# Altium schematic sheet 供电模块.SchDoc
size 381 x 241 mm; SheetNumber: 1; SheetTotal: 2
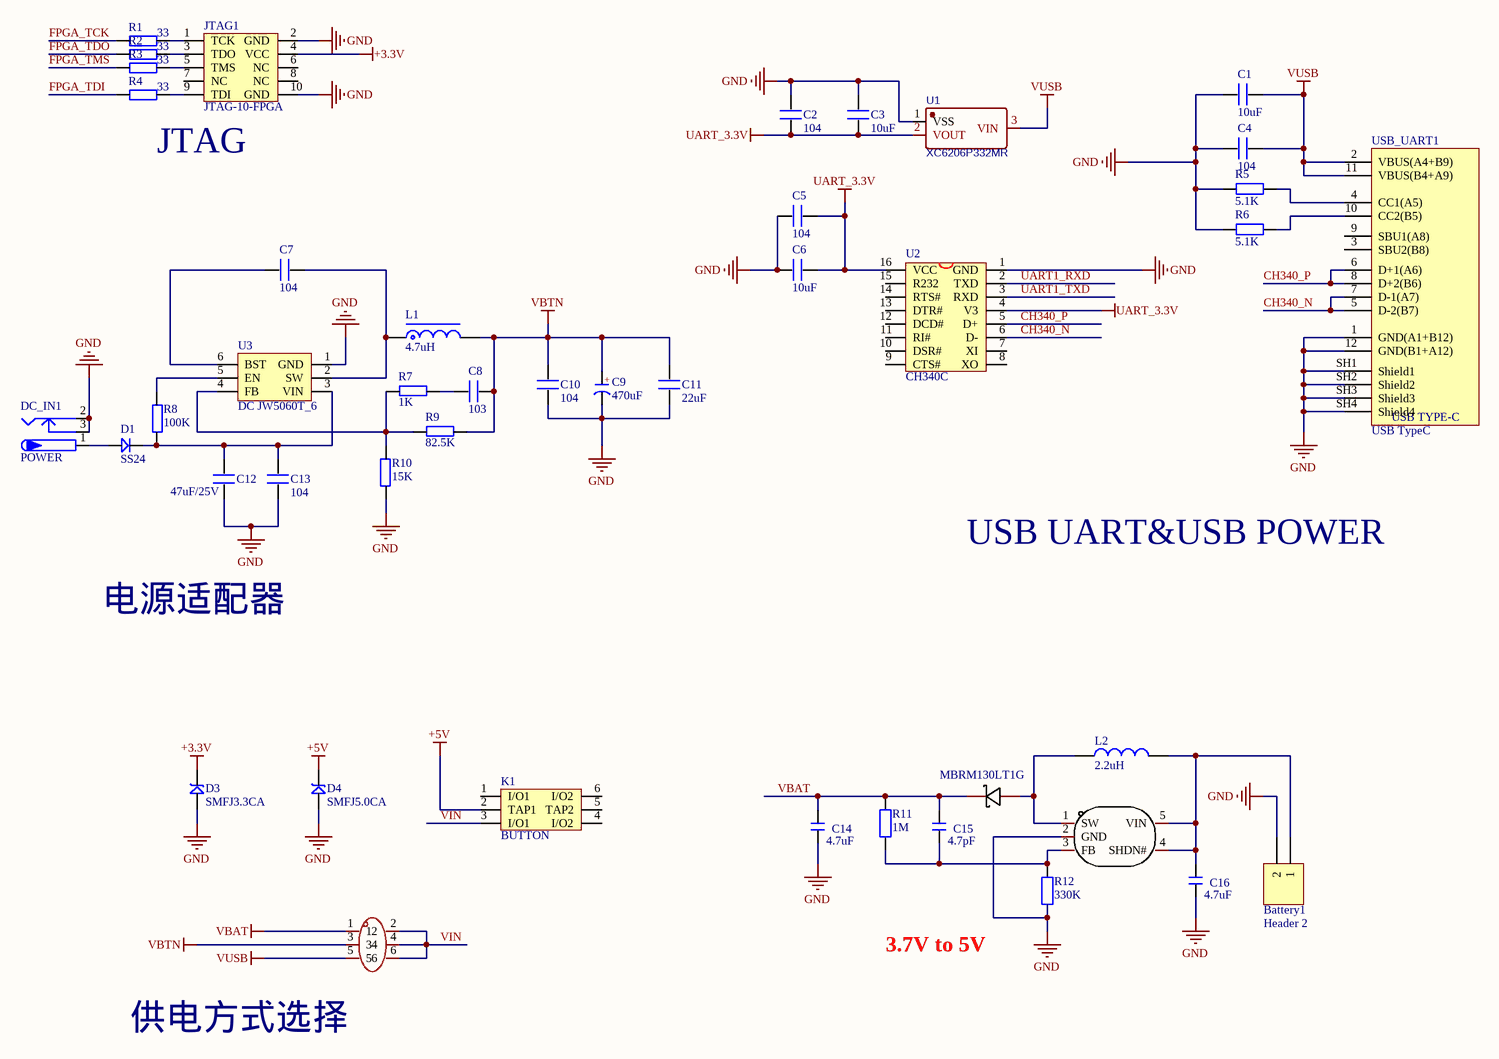
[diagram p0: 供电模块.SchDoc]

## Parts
Battery1  Header 2  [HDR1X2]
C1  10uF  [0603P]
C2  104  [0603P]
C3  10uF  [0603P]
C4  104  [0603P]
C5  104  [0603P]
C6  10uF  [0603P]
C7  104  [0603P]
C8  103  [0603P]
C9  470uF  [CM D(6.3*5.4)]
C10  104  [0603P]
C11  22uF  [0603P]
C12  47uF/25V  [0603P]
C13  104  [0603P]
C14  4.7uF  [C 0603_M]
C15  4.7pF  [C 0603_M]
C16  4.7uF  [C 0603_M]
D1  SS24  [SMA]
D2  MBRM130LT1G  [DIO-SMD_L2.0-W1.9-LS3.8-RD]
D3  SMFJ3.3CA  [SOD-123]
D4  SMFJ5.0CA  [SOD-123]
DC_IN1  POWER  [DC10B]
H1  PZ254V-12-6P  [HDR-TH_6P-P2.54-V-M-R2-C3-S2.54]  (value not drawn)
JTAG1  JTAG-10-FPGA  [HDR-IDC-SMD_10PIN-V-ROW2-COL5-PITCH2.00]
K1  BUTTON  [BTN8.5*8.5]
L1  4.7uH  [L-SMD-0420]
L2  2.2uH  [NR6028]
R1  33  [0402]
R2  33  [0402]
R3  33  [0402]
R4  33  [0402]
R5  5.1K  [R 0603_M]
R6  5.1K  [R 0603_M]
R7  1K  [0603P]
R8  100K  [0603P]
R9  82.5K  [0603P]
R10  15K  [0603P]
R11  1M  [R 0603_M]
R12  330K  [R 0603_M]
U1  XC6206P332MR  [SOT-23]
U2  CH340C  [SOP16M]
U3  DC JW5060T_6  [SOT23-6N]
U4  LM2704MF-ADJ/NOPB  [SOT-23-5_L3.0-W1.7-P0.95-LS2.8-BR]  (value not drawn)
USB_UART1  USB TypeC  [USB TYPE-C - 10*9]

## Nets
+3.3V: D3.2 JTAG1.4(VCC)
+5V: D4.2 K1.2(TAP1)
GND: Battery1.2 C1.1 C2.1 C3.1 C4.1 C5.2 C6.2 C9.2(K) C10.2 C11.2 C12.1 C13.1 C14.2 C16.2 D3.1 D4.1 DC_IN1.2 DC_IN1.3 JTAG1.2(GND) JTAG1.10(GND) R5.2 R6.2 R10.2 R12.1 U1.1(VSS) U2.1(GND) U3.1(GND) U4.2(GND) USB_UART1.1(GND(A1+B12)) USB_UART1.12(GND(B1+A12)) USB_UART1.SH1(Shield1) USB_UART1.SH2(Shield2) USB_UART1.SH3(Shield3) USB_UART1.SH4(Shield4)
UART_3.3V: C2.2 C3.2 C5.1 C6.1 U1.2(VOUT) U2.4(V3) U2.16(VCC)
VBAT: C14.1 C15.1 D2.1(C) H1.1 R11.2
VBTN: C8.1 C9.1(A) C10.1 C11.1 H1.3 L1.2 R9.1
VUSB: C1.2 C4.2 H1.5 U1.3(VIN) USB_UART1.2(VBUS(A4+B9)) USB_UART1.11(VBUS(B4+A9))
CH340_N: U2.6(D-) USB_UART1.5(D-2(B7)) USB_UART1.7(D-1(A7))
CH340_P: U2.5(D+) USB_UART1.6(D+1(A6)) USB_UART1.8(D+2(B6))
FPGA_TCK: R1.1
FPGA_TDI: R4.1
FPGA_TDO: R2.1
FPGA_TMS: R3.1
UART1_RXD: U2.2(TXD)
UART1_TXD: U2.3(RXD)
VIN: H1.2 H1.4 H1.6 K1.3(I/O1)
NetBattery1_1: Battery1.1 C16.1 L2.1 U4.4(SHDN#) U4.5(VIN)
NetC7_1: C7.1 L1.1 U3.2(SW)
NetC7_2: C7.2 U3.6(BST)
NetC8_2: C8.2 R7.1
NetC12_2: C12.2 C13.2 D1.2(K) R8.1 U3.3(VIN)
NetC15_2: C15.2 R11.1 R12.2 U4.3(FB)
NetD1_1: D1.1(A) DC_IN1.1
NetD2_2: D2.2(A) L2.2 U4.1(SW)
NetJTAG1_1: JTAG1.1(TCK) R1.2
NetJTAG1_3: JTAG1.3(TDO) R2.2
NetJTAG1_5: JTAG1.5(TMS) R3.2
NetJTAG1_9: JTAG1.9(TDI) R4.2
NetR5_1: R5.1 USB_UART1.4(CC1(A5))
NetR6_1: R6.1 USB_UART1.10(CC2(B5))
NetR7_2: R7.2 R9.2 R10.1 U3.4(FB)
NetR8_2: R8.2 U3.5(EN)

Not connected (* = marked no-connect by the designer): JTAG1 6(NC) 7(NC) 8(NC); K1 1(I/O1) 4(I/O2) 5(TAP2) 6(I/O2); U2 7(XI) 8(XO) 9(CTS#) 10(DSR#) 11(RI#) 12(DCD#) 13(DTR#) 14(RTS#) 15(R232); USB_UART1 3(SBU2(B8)) 9(SBU1(A8))

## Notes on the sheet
- JTAG
- USB UART&USB POWER
- 电源适配器
- 3.7V to 5V
- 供电方式选择

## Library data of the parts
Battery1 = Header 2: Header, 2-Pin
C1-C8 C10-C13 = C
C9 = C-CM: 贴片电解电容; 版权归属: 源创客
C14-C16 = C: 无极性贴片电容; 版权归属: 源创客
D1 = SS14: 肖特基二极管; 版权归属: 源创客; 属性: 40V/1A
D2 = MBRM130LT1G: Manufacturer: onsemi(安森美); Add into BOM: yes; Forward Voltage (Vf@If): 380mV@1A; Reverse Voltage (Vr): 30V; Average Rectified Current (Io): 1A; Reverse Leakage Current (Ir): 410uA@30V
D3 D4 = SMBJ: TVS
DC_IN1 = P-DC: 低压电源接口; BOM名称: DC电源接口; 版权归属: 源创客
H1 = PZ254V-12-6P: Manufacturer: XFCN(兴飞); Add into BOM: yes; Pin Structure: 2x3P; Pitch: 2.54mm; Circluar Pins/Square Pins: 方针
L1 = L-CDRH: 功率屏蔽电感; 版权归属: 源创客
L2 = L: 小功率贴片电感; 淘宝ID: 封装库来自淘宝 ID：黄晶宝石; 封装库来自淘宝卖家 ID：黄晶宝石: 其他店铺购入均为盗版，不享受售后技术支持服务，请立即申请退款
R1-R4 R7-R10 = R
R5 R6 R11 R12 = R: 贴片电阻; 版权归属: 来自淘宝 ID：黄晶宝石; 封装库来自淘宝卖家 ID：黄晶宝石: 其他店铺购入均为盗版，不享受售后技术支持服务，请立即申请退款
U1 = XC6206P332MR_C347376: BOM_Manufacturer: Youtai Semiconductor Co., Ltd.; Contributor: LCSC; SMT Type: Extend
U2 = CH340G: USB2UART
U3 = DC JW5060T_6: DC降压芯片
U4 = LM2704MF-ADJ/NOPB: Manufacturer: TI(德州仪器); Add into BOM: yes; Function: 升压型; Input Voltage: 2.2V~7V; Output Voltage: 20V; Output Current (Max): 550mA; Synchronous Rectification: 否; Number of Outputs: 1; Topology: 升压式; Switch tube (built-in/external): 内置
USB_UART1 = USB Type-C: 12P TypeC 母座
